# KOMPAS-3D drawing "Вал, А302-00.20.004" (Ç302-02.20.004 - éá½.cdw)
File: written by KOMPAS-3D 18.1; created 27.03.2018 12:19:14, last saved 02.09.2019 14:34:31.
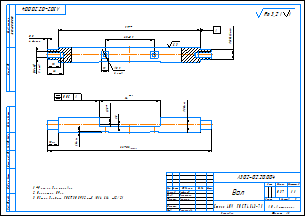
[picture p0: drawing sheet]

Sheet 1: A3, landscape

Document properties: Автор: Милов; Организация: Милов; Полное имя файла: D:\Мембранные насосы\Мембранный электропривод\А302-00.00.000 - ASTRA-302 (МЭ200)\Чертежи ПВХ\А302-02.20.004 - Вал.cdw; Масса: 0.365977; Параметр неуказанной шероховатости: Ra 3,2

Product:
- Part/product: Вал  | designation А302-00.20.004
    Материал: Сталь 40Х  ГОСТ 4543-71 (density 7825 kg/m3)
    Масса: 0.369778
    Раздел спецификации: Детали
    Форматы листов документа: A3
- Part/product: Вал  | designation А302-02.20.004
    Материал: Сталь 40Х  ГОСТ 4543-71 (density 7825 kg/m3)
    Масса: 0.365977
    Раздел спецификации: Детали
    Форматы листов документа: A3
    source file: А302-02.20.004 - Вал.cdw

Title block, sheet 1: Наименование: Вал; designation: А302-02.20.004; Материал: Сталь 40Х  ГОСТ 4543-71; Масса: 0,37; scale: 1:1; Количество листов документа: 1; organisation: АО «Астерион»; Форматы листов документа: A3; stored path: Z:\Мембранные насосы\Мембранный электропривод\А302-00.00.000 - ASTRA-302 (МЭ200)\Чертежи\А302-00.20.004 - Вал.cdw; Разработал: Лифлянд; Проверил: Борисенко; Т. контр.: Лучихин; Утвердил: Григорьева

Views: Вид 1, Спереди, Проекционный вид 2, Местный разрез 1, Местный разрез 2
Referenced files in Z:\Мембранные насосы\Мембранный электропривод\А302-00.00.000 - ASTRA-302 (МЭ200)\3Д\: А302-00.20.004 - Вал.m3d
Referenced files in D:\Мембранные насосы\Мембранный электропривод\А302-00.00.000 - ASTRA-302 (МЭ200)\3Д\: А302-00.20.004 - Вал.m3d
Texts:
  Ra 3,2
  Ra 3,2 ( )
Dimensions and other numbers on the sheet: 227; 15; 1,5; 84; 0,05; 20; 2,5; 12,5; 68±0,1; 5,1; 2 отв.; -6Н; 8; 0,5; 4 фаски; 18; 22; 197; 6,3; 13,5; 11; 1:1; 1; 0,37

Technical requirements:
  *Размер для справок.
  Покрытие: Ц9хр.
  Общие допуски ГОСТ 30893.2-mK (H14, h14,  t2/2).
